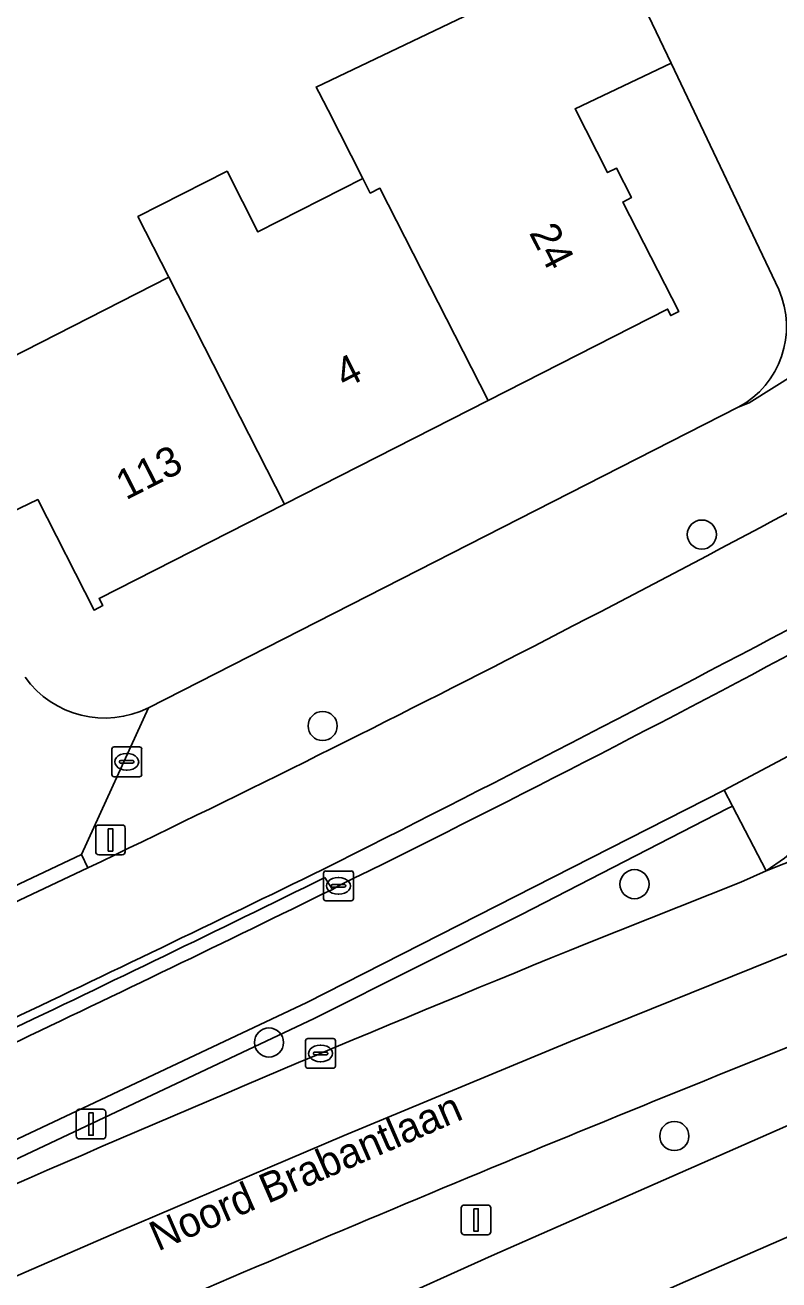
# Model space of a CAD drawing. Extents: x 158352 to 159489, y 383828 to 384603.
# Drawn here: x 159093.01 to 159118.3, y 383933 to 383975.15 of the extents above; entities that cross this region are included whole.
import ezdxf

# ---------------------------------------------------------------- set-up
doc = ezdxf.new("R2010")
doc.units = 0
for name, color, linetype in [('IMGEO_Berm_groen', 7, 'Continuous'), ('IMGEO_Berm_open', 7, 'Continuous'), ('IMGEO_Boom', 7, 'Continuous'), ('IMGEO_Brandkraan', 7, 'Continuous'), ('IMGEO_Erf', 7, 'Continuous'), ('IMGEO_Fietspad_gesloten', 7, 'Continuous'), ('IMGEO_Groenvoorziening', 7, 'Continuous'), ('IMGEO_Haag', 7, 'Continuous'), ('IMGEO_Kolk', 7, 'Continuous'), ('IMGEO_Lichtmast', 7, 'Continuous'), ('IMGEO_Openbare_ruimte_label', 7, 'Continuous'), ('IMGEO_OVBaan_gesloten', 7, 'Continuous'), ('IMGEO_Pand', 7, 'Continuous'), ('IMGEO_Pand_nummerreeks', 7, 'Continuous'), ('IMGEO_Rijbaan_lokaal_open', 7, 'Continuous'), ('IMGEO_Rijbaan_regionaal_gesloten', 7, 'Continuous'), ('IMGEO_Verkeersbordpaal', 7, 'Continuous'), ('IMGEO_Voetpad_open', 7, 'Continuous')]:
    doc.layers.add(name, color=color, linetype=linetype)

msp = doc.modelspace()

# ---------------------------------------------------------------- linework, layer by layer
at = {"layer": 'IMGEO_Berm_groen'}
for points in [[(159111.88, 383944.314), (159117.025, 383946.362), (159117.879, 383946.744), (159116.748, 383948.92), (159116.585, 383948.835), (159109.671, 383945.276), (159102.708, 383941.782), (159083.15, 383932.545), (159082.522, 383932.248), (159082.037, 383932.044), (159081.013, 383931.679), (159079.958, 383931.391), (159078.884, 383931.185), (159077.797, 383931.061), (159076.704, 383931.02), (159075.634, 383931.062)], [(159108.657, 383933.813), (159126.432, 383941.634)], [(159093.279, 383930.202), (159085.894, 383926.817), (159076.317, 383922.427), (159065.564, 383917.209), (159062.868, 383915.915), (159061.206, 383911.809), (159065.096, 383913.62), (159069.31, 383915.653), (159087.254, 383923.978), (159101.121, 383930.412), (159108.657, 383933.813)]]:
    msp.add_lwpolyline(points, dxfattribs=at)
for centre, radius, start, end in [((159416.982, 383193.55), 810.391, 112.116276, 113.599521), ((159430.359, 383161.648), 839.225, 111.70335, 113.681786)]:
    msp.add_arc(centre, radius, start, end, dxfattribs=at)
at = {"layer": 'IMGEO_Berm_open'}
msp.add_lwpolyline([(159103.066, 383946.52), (159103.319, 383946.123), (159103.526, 383946.238)], dxfattribs=at)
for centre, radius, start, end in [((158726.741, 384695.036), 837.522, 296.695392, 297.973551), ((158872.032, 384415.747), 523.477, 296.24585, 298.26665), ((158605.342, 384966.195), 1134.394, 294.805887, 296.020632), ((158714.959, 384732.93), 876.965, 294.699373, 296.267148)]:
    msp.add_arc(centre, radius, start, end, dxfattribs=at)
at = {"layer": 'IMGEO_Boom'}
for centre in [(159115.719, 383958.039), (159102.994, 383951.611), (159113.459, 383946.296), (159101.193, 383940.979), (159114.797, 383937.836)]:
    msp.add_circle(centre, 0.489, dxfattribs=at)
at = {"layer": 'IMGEO_Brandkraan'}
for p, q in [((159095.919, 383949.981), (159095.919, 383950.833)), ((159095.994, 383950.907), (159096.846, 383950.907)), ((159096.92, 383950.833), (159096.92, 383949.981)), ((159096.178, 383950.401), (159096.178, 383950.413)), ((159096.221, 383950.45), (159096.619, 383950.45)), ((159096.407, 383950.687), (159096.432, 383950.687)), ((159096.662, 383950.413), (159096.662, 383950.401)), ((159096.616, 383950.364), (159096.218, 383950.364)), ((159096.43, 383950.127), (159096.405, 383950.127)), ((159096.846, 383949.907), (159095.994, 383949.907))]:
    msp.add_line(p, q, dxfattribs=at)
for points in [[(159095.919, 383949.981), (159095.919, 383950.833)], [(159095.994, 383950.907), (159096.846, 383950.907)], [(159096.92, 383950.833), (159096.92, 383949.981)], [(159096.846, 383949.907), (159095.994, 383949.907)]]:
    msp.add_lwpolyline(points, dxfattribs=at)
for centre, radius, start, end in [((159095.996, 383950.831), 0.0765, 91.552, 178.448), ((159095.996, 383950.831), 0.0765, 91.552, 178.448), ((159096.844, 383950.831), 0.0765, 1.552, 88.448), ((159096.844, 383950.831), 0.0765, 1.552, 88.448), ((159096.218, 383950.41), 0.0403, 85.8775, 175.7526), ((159096.623, 383950.412), 0.0386, 1.7309, 96.639), ((159096.215, 383950.4), 0.0366, 178.938, 274.7102), ((159096.619, 383950.407), 0.043, 264.8664, 352.4533), ((159095.996, 383949.983), 0.0765, 181.552, 268.448), ((159095.996, 383949.983), 0.0765, 181.552, 268.448), ((159096.844, 383949.983), 0.0765, 271.552, 358.448), ((159096.844, 383949.983), 0.0765, 271.552, 358.448)]:
    msp.add_arc(centre, radius, start, end, dxfattribs=at)
for centre, major_axis, ratio, start_param, end_param in [((159096.406, 383950.407), (-0.387, 0.002), 0.722429, 4.712389, 7.853982), ((159096.431, 383950.407), (-0.39, 0.002), 0.717154, 1.570796, 4.712389)]:
    msp.add_ellipse(centre, major_axis=major_axis, ratio=ratio, start_param=start_param, end_param=end_param, dxfattribs=at)
at = {"layer": 'IMGEO_Erf'}
for points in [[(159094.462, 383982.872), (159086.359, 383967.77), (159092.461, 383963.945), (159097.832, 383966.681), (159096.794, 383968.719), (159099.786, 383970.243), (159100.824, 383968.205), (159104.342, 383969.997), (159103.174, 383972.291), (159102.861, 383972.905), (159102.775, 383973.072), (159108.99, 383976.042)], [(159118.298, 383966.268), (159114.689, 383973.875), (159111.467, 383972.336), (159112.556, 383970.196), (159112.855, 383970.348), (159113.358, 383969.359), (159113.066, 383969.21), (159114.942, 383965.529), (159114.678, 383965.395), (159114.567, 383965.614), (159108.545, 383962.547), (159101.711, 383959.065), (159095.489, 383955.896), (159095.613, 383955.652), (159095.325, 383955.505), (159093.434, 383959.217), (159090.422, 383957.777), (159086.423, 383960.897)], [(159097.149, 383952.222), (159116.943, 383962.316)]]:
    msp.add_lwpolyline(points, dxfattribs=at)
for centre, radius, start, end in [((159115.494, 383965.021), 3.069, 298.1724, 23.9776), ((159095.68, 383955.166), 3.29, 215.7275, 296.5128)]:
    msp.add_arc(centre, radius, start, end, dxfattribs=at)
at = {"layer": 'IMGEO_Fietspad_gesloten'}
msp.add_lwpolyline([(159095.116, 383946.845), (159085.525, 383942.307), (159079.821, 383939.628), (159080.638, 383937.84), (159081.272, 383936.466)], dxfattribs=at)
for centre, radius, start, end in [((158837.65, 384482.967), 594.74, 295.652031, 298.772461), ((158726.741, 384695.036), 837.522, 296.695392, 297.973551), ((158605.342, 384966.195), 1134.394, 294.805887, 296.020632)]:
    msp.add_arc(centre, radius, start, end, dxfattribs=at)
at = {"layer": 'IMGEO_Groenvoorziening'}
for points in [[(159116.585, 383948.835), (159116.748, 383948.92), (159116.471, 383949.452), (159102.458, 383942.327), (159082.891, 383933.086), (159082.277, 383932.796)], [(159075.634, 383931.062), (159076.704, 383931.02), (159077.797, 383931.061), (159078.884, 383931.185), (159079.958, 383931.391), (159081.013, 383931.679), (159082.037, 383932.044), (159082.522, 383932.248), (159083.15, 383932.545), (159102.708, 383941.782), (159109.671, 383945.276), (159116.585, 383948.835)]]:
    msp.add_lwpolyline(points, dxfattribs=at)
at = {"layer": 'IMGEO_Haag'}
for points in [[(159116.585, 383948.835), (159116.748, 383948.92), (159116.471, 383949.452), (159102.458, 383942.327), (159082.891, 383933.086), (159082.277, 383932.796)], [(159075.634, 383931.062), (159076.704, 383931.02), (159077.797, 383931.061), (159078.884, 383931.185), (159079.958, 383931.391), (159081.013, 383931.679), (159082.037, 383932.044), (159082.522, 383932.248), (159083.15, 383932.545), (159102.708, 383941.782), (159109.671, 383945.276), (159116.585, 383948.835)]]:
    msp.add_lwpolyline(points, dxfattribs=at)
at = {"layer": 'IMGEO_Kolk'}
for p, q in [((159103.025, 383945.813), (159103.025, 383946.665)), ((159103.1, 383946.739), (159103.952, 383946.739)), ((159104.026, 383946.665), (159104.026, 383945.813)), ((159103.284, 383946.233), (159103.284, 383946.245)), ((159103.722, 383946.196), (159103.324, 383946.196)), ((159103.327, 383946.282), (159103.725, 383946.282)), ((159103.513, 383946.519), (159103.538, 383946.519)), ((159103.768, 383946.245), (159103.768, 383946.233)), ((159103.536, 383945.959), (159103.511, 383945.959)), ((159103.952, 383945.739), (159103.1, 383945.739)), ((159102.423, 383940.187), (159102.423, 383941.039)), ((159102.498, 383941.113), (159103.35, 383941.113)), ((159102.911, 383940.893), (159102.936, 383940.893)), ((159103.424, 383941.039), (159103.424, 383940.187)), ((159102.682, 383940.607), (159102.682, 383940.619)), ((159103.12, 383940.57), (159102.722, 383940.57)), ((159102.725, 383940.656), (159103.123, 383940.656)), ((159102.934, 383940.333), (159102.909, 383940.333)), ((159103.166, 383940.619), (159103.166, 383940.607)), ((159103.35, 383940.113), (159102.498, 383940.113))]:
    msp.add_line(p, q, dxfattribs=at)
for points in [[(159103.025, 383945.813), (159103.025, 383946.665)], [(159103.1, 383946.739), (159103.952, 383946.739)], [(159104.026, 383946.665), (159104.026, 383945.813)], [(159103.952, 383945.739), (159103.1, 383945.739)], [(159102.423, 383940.187), (159102.423, 383941.039)], [(159102.498, 383941.113), (159103.35, 383941.113)], [(159103.424, 383941.039), (159103.424, 383940.187)], [(159103.35, 383940.113), (159102.498, 383940.113)]]:
    msp.add_lwpolyline(points, dxfattribs=at)
for centre, radius, start, end in [((159103.102, 383946.663), 0.0765, 91.552, 178.448), ((159103.102, 383946.663), 0.0765, 91.552, 178.448), ((159103.95, 383946.663), 0.0765, 1.552, 88.448), ((159103.95, 383946.663), 0.0765, 1.552, 88.448), ((159103.324, 383946.242), 0.0403, 85.8775, 175.7526), ((159103.321, 383946.232), 0.0366, 178.938, 274.7102), ((159103.725, 383946.239), 0.043, 264.8664, 352.4533), ((159103.729, 383946.244), 0.0386, 1.7309, 96.639), ((159103.102, 383945.815), 0.0765, 181.552, 268.448), ((159103.102, 383945.815), 0.0765, 181.552, 268.448), ((159103.95, 383945.815), 0.0765, 271.552, 358.448), ((159103.95, 383945.815), 0.0765, 271.552, 358.448), ((159102.5, 383941.037), 0.0765, 91.552, 178.448), ((159102.5, 383941.037), 0.0765, 91.552, 178.448), ((159103.348, 383941.037), 0.0765, 1.552, 88.448), ((159103.348, 383941.037), 0.0765, 1.552, 88.448), ((159102.722, 383940.616), 0.0403, 85.8775, 175.7526), ((159102.719, 383940.606), 0.0366, 178.938, 274.7102), ((159103.123, 383940.613), 0.043, 264.8664, 352.4533), ((159103.127, 383940.618), 0.0386, 1.7309, 96.639), ((159102.5, 383940.189), 0.0765, 181.552, 268.448), ((159102.5, 383940.189), 0.0765, 181.552, 268.448), ((159103.348, 383940.189), 0.0765, 271.552, 358.448), ((159103.348, 383940.189), 0.0765, 271.552, 358.448)]:
    msp.add_arc(centre, radius, start, end, dxfattribs=at)
for centre, major_axis, ratio, start_param, end_param in [((159103.512, 383946.239), (-0.387, 0.002), 0.722429, 4.712389, 7.853982), ((159103.537, 383946.239), (-0.39, 0.002), 0.717154, 1.570796, 4.712389), ((159102.91, 383940.613), (-0.387, 0.002), 0.722429, 4.712389, 7.853982), ((159102.935, 383940.613), (-0.39, 0.002), 0.717154, 1.570796, 4.712389)]:
    msp.add_ellipse(centre, major_axis=major_axis, ratio=ratio, start_param=start_param, end_param=end_param, dxfattribs=at)
at = {"layer": 'IMGEO_Lichtmast'}
for p, q in [((159095.378, 383947.383), (159095.378, 383948.183)), ((159095.378, 383948.183), (159095.378, 383947.383)), ((159095.478, 383948.283), (159096.268, 383948.283)), ((159096.268, 383948.283), (159095.478, 383948.283)), ((159096.368, 383948.183), (159096.368, 383947.383)), ((159096.368, 383947.383), (159096.368, 383948.183)), ((159096.268, 383947.283), (159095.478, 383947.283)), ((159095.478, 383947.283), (159096.268, 383947.283)), ((159107.644, 383934.62), (159107.644, 383935.42)), ((159107.644, 383935.42), (159107.644, 383934.62)), ((159107.744, 383935.52), (159108.534, 383935.52)), ((159108.534, 383935.52), (159107.744, 383935.52)), ((159108.634, 383935.42), (159108.634, 383934.62)), ((159108.634, 383934.62), (159108.634, 383935.42)), ((159108.534, 383934.52), (159107.744, 383934.52)), ((159107.744, 383934.52), (159108.534, 383934.52))]:
    msp.add_line(p, q, dxfattribs=at)
for points in [[(159095.798, 383948.158), (159095.948, 383948.158), (159095.948, 383947.408), (159095.798, 383947.408), (159095.798, 383948.158)], [(159108.064, 383935.395), (159108.214, 383935.395), (159108.214, 383934.645), (159108.064, 383934.645), (159108.064, 383935.395)]]:
    msp.add_lwpolyline(points, dxfattribs=at)
for centre, start, end in [((159095.478, 383948.183), 90, 180), ((159095.478, 383948.183), 90, 180), ((159096.268, 383948.183), 0, 90), ((159096.268, 383948.183), 360, 90), ((159095.478, 383947.383), 180, 270), ((159095.478, 383947.383), 180, 270), ((159096.268, 383947.383), 270, 0), ((159096.268, 383947.383), 270, 0), ((159107.744, 383935.42), 90, 180), ((159107.744, 383935.42), 90, 180), ((159108.534, 383935.42), 0, 90), ((159108.534, 383935.42), 360, 90), ((159107.744, 383934.62), 180, 270), ((159107.744, 383934.62), 180, 270), ((159108.534, 383934.62), 270, 0), ((159108.534, 383934.62), 270, 0)]:
    msp.add_arc(centre, 0.1, start, end, dxfattribs=at)
at = {"layer": 'IMGEO_OVBaan_gesloten'}
for points in [[(159126.432, 383941.634), (159108.657, 383933.813), (159101.121, 383930.412), (159087.254, 383923.978), (159088.723, 383920.864), (159106.524, 383929.105), (159114.987, 383932.875), (159131.365, 383940.018), (159135.412, 383941.71), (159141.76, 383944.286), (159150.327, 383947.686), (159158.923, 383951.012), (159167.548, 383954.263), (159167.948, 383954.404), (159176.741, 383957.59), (159186.124, 383960.762), (159200.451, 383965.355), (159220.559, 383971.289), (159230.686, 383974.033)], [(159089.779, 383918.626), (159098.804, 383922.7), (159153.667, 383947.467), (159198.04, 383963.118), (159231.334, 383971.446), (159230.686, 383974.033), (159220.559, 383971.289), (159200.451, 383965.355), (159186.124, 383960.762), (159176.741, 383957.59), (159167.948, 383954.404), (159167.548, 383954.263), (159158.923, 383951.012), (159150.327, 383947.686), (159141.76, 383944.286), (159135.412, 383941.71), (159131.365, 383940.018), (159114.987, 383932.875), (159106.524, 383929.105), (159088.723, 383920.864), (159089.779, 383918.626)]]:
    msp.add_lwpolyline(points, dxfattribs=at)
at = {"layer": 'IMGEO_Pand'}
for points in [[(159114.689, 383973.875), (159112.786, 383977.856), (159109.448, 383976.261), (159108.99, 383976.042), (159102.775, 383973.072), (159102.861, 383972.905), (159103.174, 383972.291), (159104.342, 383969.997), (159104.591, 383969.509), (159104.915, 383969.674), (159108.545, 383962.547), (159114.567, 383965.614), (159114.678, 383965.395), (159114.942, 383965.529), (159113.066, 383969.21), (159113.358, 383969.359), (159112.855, 383970.348), (159112.556, 383970.196), (159111.467, 383972.336)], [(159097.832, 383966.681), (159101.711, 383959.065), (159108.545, 383962.547), (159104.915, 383969.674), (159104.591, 383969.509), (159104.342, 383969.997), (159100.824, 383968.205), (159099.786, 383970.243), (159096.794, 383968.719)], [(159097.832, 383966.681), (159092.461, 383963.945), (159086.359, 383967.77), (159086.036, 383967.168), (159083.673, 383962.761), (159086.423, 383960.897), (159090.422, 383957.777), (159093.434, 383959.217), (159095.325, 383955.505), (159095.613, 383955.652), (159095.489, 383955.896), (159101.711, 383959.065)]]:
    msp.add_lwpolyline(points, close=True, dxfattribs=at)
at = {"layer": 'IMGEO_Rijbaan_lokaal_open'}
for points in [[(159081.592, 383935.798), (159082.891, 383933.086), (159102.458, 383942.327), (159116.471, 383949.452), (159125.435, 383954.227), (159136.64, 383960.422), (159162.338, 383975.274)], [(159125.218, 383952.808), (159118.496, 383947.165), (159117.879, 383946.744), (159122.508, 383948.581), (159134.734, 383953.486), (159147.488, 383958.572), (159153.947, 383961.013), (159153.824, 383961.333)], [(159103.526, 383946.238), (159103.319, 383946.123)]]:
    msp.add_lwpolyline(points, dxfattribs=at)
for centre, radius, start, end in [((158872.032, 384415.747), 523.477, 296.24585, 298.26665), ((158694.716, 384777.928), 926.745, 294.674142, 296.161411)]:
    msp.add_arc(centre, radius, start, end, dxfattribs=at)
at = {"layer": 'IMGEO_Rijbaan_regionaal_gesloten'}
for points in [[(159201.753, 383977.525), (159197.902, 383976.19), (159194.999, 383975.26), (159181.375, 383970.853), (159173.957, 383968.297), (159165.044, 383965.227), (159162.413, 383964.212), (159153.947, 383961.013), (159147.488, 383958.572), (159134.734, 383953.486), (159122.508, 383948.581), (159117.879, 383946.744), (159117.025, 383946.362), (159111.88, 383944.314)], [(159083.379, 383932.066), (159084.637, 383929.44), (159092.077, 383932.858), (159096.157, 383934.635), (159103.717, 383937.859), (159111.311, 383941.012), (159118.775, 383944.025), (159146.161, 383954.982), (159156.981, 383959.13), (159166.881, 383962.821), (159177.597, 383966.534), (159185.178, 383969.076), (159192.782, 383971.541), (159196.822, 383972.81), (159202.97, 383974.661), (159205.85, 383975.797)], [(159205.85, 383975.797), (159202.97, 383974.661), (159196.822, 383972.81), (159192.782, 383971.541), (159185.178, 383969.076), (159177.597, 383966.534), (159166.881, 383962.821), (159156.981, 383959.13), (159146.161, 383954.982), (159118.775, 383944.025), (159111.311, 383941.012), (159103.717, 383937.859), (159096.157, 383934.635), (159092.077, 383932.858), (159084.637, 383929.44), (159085.894, 383926.817), (159093.279, 383930.202)]]:
    msp.add_lwpolyline(points, dxfattribs=at)
for centre, radius, start, end in [((159416.982, 383193.55), 810.391, 112.116276, 113.599521), ((159430.359, 383161.648), 839.225, 111.70335, 113.681786)]:
    msp.add_arc(centre, radius, start, end, dxfattribs=at)
at = {"layer": 'IMGEO_Verkeersbordpaal'}
for p, q in [((159094.724, 383937.84), (159094.724, 383938.64)), ((159094.724, 383938.64), (159094.724, 383937.84)), ((159094.824, 383938.74), (159095.614, 383938.74)), ((159095.614, 383938.74), (159094.824, 383938.74)), ((159095.714, 383938.64), (159095.714, 383937.84)), ((159095.714, 383937.84), (159095.714, 383938.64)), ((159095.614, 383937.74), (159094.824, 383937.74)), ((159094.824, 383937.74), (159095.614, 383937.74))]:
    msp.add_line(p, q, dxfattribs=at)
msp.add_lwpolyline([(159095.144, 383938.615), (159095.294, 383938.615), (159095.294, 383937.865), (159095.144, 383937.865), (159095.144, 383938.615)], dxfattribs=at)
for centre, start, end in [((159094.824, 383938.64), 90, 180), ((159094.824, 383938.64), 90, 180), ((159095.614, 383938.64), 0, 90), ((159095.614, 383938.64), 360, 90), ((159094.824, 383937.84), 180, 270), ((159094.824, 383937.84), 180, 270), ((159095.614, 383937.84), 270, 0), ((159095.614, 383937.84), 270, 0)]:
    msp.add_arc(centre, 0.1, start, end, dxfattribs=at)
at = {"layer": 'IMGEO_Voetpad_open'}
for points in [[(159114.367, 383984.335), (159113.209, 383986.675), (159112.272, 383986.223), (159107.508, 383996.103), (159108.445, 383996.555), (159107.692, 383998.149), (159106.856, 384000), (159106.293, 384001.308), (159105.793, 384002.367), (159094.975, 384024.761), (159092.289, 384029.829), (159089.901, 384028.605), (159091.357, 384025.766), (159103.494, 384000), (159105.742, 383995.228), (159103.84, 383994.336), (159105.907, 383989.923), (159107.077, 383987.424), (159108.284, 383984.848), (159109.173, 383985.415), (159111.239, 383981.094), (159112.786, 383977.856), (159114.689, 383973.875), (159118.298, 383966.268)], [(159116.943, 383962.316), (159117.307, 383962.466), (159122.907, 383965.977), (159122.664, 383966.557), (159121.805, 383968.367), (159121.286, 383969.447), (159118.479, 383975.731), (159114.367, 383984.335)], [(159123.918, 383961.655), (159123.411, 383962.563), (159128.956, 383965.658), (159126.514, 383967.708), (159122.907, 383965.977), (159117.307, 383962.466), (159116.943, 383962.316), (159097.149, 383952.222), (159094.903, 383947.296), (159095.116, 383946.845)], [(159080.108, 383958.921), (159080.334, 383957.936), (159080.456, 383957.575), (159080.843, 383957.806), (159081.266, 383957.181), (159083.722, 383955.442), (159083.469, 383955.061), (159084.554, 383954.282), (159085.114, 383953.948), (159085.619, 383953.603), (159083.992, 383951.603), (159090.108, 383945.027), (159094.903, 383947.296), (159097.149, 383952.222)], [(159125.964, 383953.244), (159125.862, 383953.434), (159125.435, 383954.227), (159116.471, 383949.452), (159116.748, 383948.92), (159117.879, 383946.744), (159118.496, 383947.165), (159125.218, 383952.808)], [(159103.319, 383946.123), (159103.066, 383946.52)]]:
    msp.add_lwpolyline(points, dxfattribs=at)
msp.add_lwpolyline([(159094.903, 383947.296), (159090.108, 383945.027), (159085.312, 383942.758), (159085.525, 383942.307), (159095.116, 383946.845)], close=True, dxfattribs=at)
for centre, radius, start, end in [((159115.494, 383965.021), 3.069, 298.1724, 23.9776), ((158837.65, 384482.967), 594.74, 295.652031, 298.772461), ((159095.68, 383955.166), 3.29, 215.7275, 296.5128), ((158714.959, 384732.93), 876.965, 294.699373, 296.267148), ((158694.716, 384777.928), 926.745, 294.674142, 296.161411)]:
    msp.add_arc(centre, radius, start, end, dxfattribs=at)

# ---------------------------------------------------------------- texts
at = {"layer": 'IMGEO_Openbare_ruimte_label'}
msp.add_text('Noord Brabantlaan', height=1, rotation=23.462, dxfattribs=at).set_placement((159097.467, 383933.956))
at = {"layer": 'IMGEO_Pand_nummerreeks'}
for s, rotation, p in [('24', 297.0434, (159109.908, 383968.177)), ('4', 26.9935, (159103.74, 383962.927)), ('113', 26.9935, (159096.391, 383959.184))]:
    msp.add_text(s, height=1, rotation=rotation, dxfattribs=at).set_placement(p)

doc.saveas('drawing.dxf')
